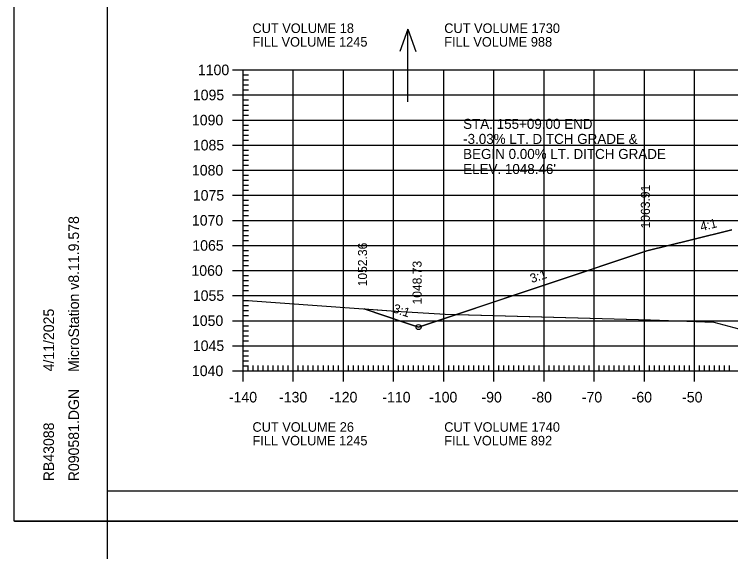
# Model space of a CAD drawing. Extents: x 1322838 to 1324533, y 339903 to 351025.
# Drawn here: x 1323450 to 1323592.8, y 344818.1 to 344925.2 of the extents above; entities that cross this region are included whole.
import ezdxf

# ---------------------------------------------------------------- set-up
doc = ezdxf.new("R2010")
doc.units = 0
for name, color, linetype in [('R_Axis', 7, 'Continuous'), ('R_Axis Annot', 7, 'Continuous'), ('R_Border', 7, 'Continuous'), ('R_Drive', 7, 'Continuous'), ('R_Exist Surface', 7, 'Continuous'), ('R_Fin Surface', 7, 'Continuous'), ('R_Grid', 7, 'Continuous'), ('R_No Plot', 7, 'Continuous'), ('R_Water Annot', 7, 'Continuous'), ('R_Xsect Elev', 7, 'Continuous'), ('R_Xsect Slope', 7, 'Continuous')]:
    doc.layers.add(name, color=color, linetype=linetype)

msp = doc.modelspace()

# ---------------------------------------------------------------- linework, layer by layer
at = {"layer": 'R_Axis'}
for p, q in [((1323493.48, 344914.14), (1323497.68, 344914.14)), ((1323495.58, 344854.14), (1323495.58, 344914.14)), ((1323495.58, 344913.14), (1323496.63, 344913.14)), ((1323495.58, 344912.14), (1323496.63, 344912.14)), ((1323495.58, 344911.14), (1323496.63, 344911.14)), ((1323495.58, 344910.14), (1323496.63, 344910.14)), ((1323493.48, 344909.14), (1323497.68, 344909.14)), ((1323495.58, 344908.14), (1323496.63, 344908.14)), ((1323495.58, 344907.14), (1323496.63, 344907.14)), ((1323495.58, 344906.14), (1323496.63, 344906.14)), ((1323495.58, 344905.14), (1323496.63, 344905.14)), ((1323493.48, 344904.14), (1323497.68, 344904.14)), ((1323495.58, 344903.14), (1323496.63, 344903.14)), ((1323495.58, 344902.14), (1323496.63, 344902.14)), ((1323495.58, 344901.14), (1323496.63, 344901.14)), ((1323495.58, 344900.14), (1323496.63, 344900.14)), ((1323493.48, 344899.14), (1323497.68, 344899.14)), ((1323495.58, 344898.14), (1323496.63, 344898.14)), ((1323495.58, 344897.14), (1323496.63, 344897.14)), ((1323495.58, 344896.14), (1323496.63, 344896.14)), ((1323495.58, 344895.14), (1323496.63, 344895.14)), ((1323493.48, 344894.14), (1323497.68, 344894.14)), ((1323495.58, 344893.14), (1323496.63, 344893.14)), ((1323495.58, 344892.14), (1323496.63, 344892.14)), ((1323495.58, 344891.14), (1323496.63, 344891.14)), ((1323495.58, 344890.14), (1323496.63, 344890.14)), ((1323493.48, 344889.14), (1323497.68, 344889.14)), ((1323495.58, 344888.14), (1323496.63, 344888.14)), ((1323495.58, 344887.14), (1323496.63, 344887.14)), ((1323495.58, 344886.14), (1323496.63, 344886.14)), ((1323495.58, 344885.14), (1323496.63, 344885.14)), ((1323493.48, 344884.14), (1323497.68, 344884.14)), ((1323495.58, 344883.14), (1323496.63, 344883.14)), ((1323495.58, 344882.14), (1323496.63, 344882.14)), ((1323495.58, 344881.14), (1323496.63, 344881.14)), ((1323495.58, 344880.14), (1323496.63, 344880.14)), ((1323493.48, 344879.14), (1323497.68, 344879.14)), ((1323495.58, 344878.14), (1323496.63, 344878.14)), ((1323495.58, 344877.14), (1323496.63, 344877.14)), ((1323495.58, 344876.14), (1323496.63, 344876.14)), ((1323495.58, 344875.14), (1323496.63, 344875.14)), ((1323493.48, 344874.14), (1323497.68, 344874.14)), ((1323495.58, 344873.14), (1323496.63, 344873.14)), ((1323495.58, 344872.14), (1323496.63, 344872.14)), ((1323495.58, 344871.14), (1323496.63, 344871.14)), ((1323495.58, 344870.14), (1323496.63, 344870.14)), ((1323493.48, 344869.14), (1323497.68, 344869.14)), ((1323495.58, 344868.14), (1323496.63, 344868.14)), ((1323495.58, 344867.14), (1323496.63, 344867.14)), ((1323495.58, 344866.14), (1323496.63, 344866.14)), ((1323495.58, 344865.14), (1323496.63, 344865.14)), ((1323493.48, 344864.14), (1323497.68, 344864.14)), ((1323495.58, 344863.14), (1323496.63, 344863.14)), ((1323495.58, 344862.14), (1323496.63, 344862.14)), ((1323495.58, 344861.14), (1323496.63, 344861.14)), ((1323495.58, 344860.14), (1323496.63, 344860.14)), ((1323493.48, 344859.14), (1323497.68, 344859.14)), ((1323495.58, 344858.14), (1323496.63, 344858.14)), ((1323495.58, 344857.14), (1323496.63, 344857.14)), ((1323495.58, 344852.04), (1323495.58, 344856.24)), ((1323495.58, 344856.14), (1323496.63, 344856.14)), ((1323495.58, 344855.14), (1323496.63, 344855.14)), ((1323496.58, 344854.14), (1323496.58, 344855.19)), ((1323497.58, 344854.14), (1323497.58, 344855.19)), ((1323498.58, 344854.14), (1323498.58, 344855.19)), ((1323499.58, 344854.14), (1323499.58, 344855.19)), ((1323500.58, 344854.14), (1323500.58, 344855.19)), ((1323501.58, 344854.14), (1323501.58, 344855.19)), ((1323502.58, 344854.14), (1323502.58, 344855.19)), ((1323503.58, 344854.14), (1323503.58, 344855.19)), ((1323504.58, 344854.14), (1323504.58, 344855.19)), ((1323505.58, 344852.04), (1323505.58, 344856.24)), ((1323506.58, 344854.14), (1323506.58, 344855.19)), ((1323507.58, 344854.14), (1323507.58, 344855.19)), ((1323508.58, 344854.14), (1323508.58, 344855.19)), ((1323509.58, 344854.14), (1323509.58, 344855.19)), ((1323510.58, 344854.14), (1323510.58, 344855.19)), ((1323511.58, 344854.14), (1323511.58, 344855.19)), ((1323512.58, 344854.14), (1323512.58, 344855.19)), ((1323513.58, 344854.14), (1323513.58, 344855.19)), ((1323514.58, 344854.14), (1323514.58, 344855.19)), ((1323515.58, 344852.04), (1323515.58, 344856.24)), ((1323516.58, 344854.14), (1323516.58, 344855.19)), ((1323517.58, 344854.14), (1323517.58, 344855.19)), ((1323518.58, 344854.14), (1323518.58, 344855.19)), ((1323519.58, 344854.14), (1323519.58, 344855.19)), ((1323520.58, 344854.14), (1323520.58, 344855.19)), ((1323521.58, 344854.14), (1323521.58, 344855.19)), ((1323522.58, 344854.14), (1323522.58, 344855.19)), ((1323523.58, 344854.14), (1323523.58, 344855.19)), ((1323524.58, 344854.14), (1323524.58, 344855.19)), ((1323525.58, 344852.04), (1323525.58, 344856.24)), ((1323526.58, 344854.14), (1323526.58, 344855.19)), ((1323527.58, 344854.14), (1323527.58, 344855.19)), ((1323528.58, 344854.14), (1323528.58, 344855.19)), ((1323529.58, 344854.14), (1323529.58, 344855.19)), ((1323530.58, 344854.14), (1323530.58, 344855.19)), ((1323531.58, 344854.14), (1323531.58, 344855.19)), ((1323532.58, 344854.14), (1323532.58, 344855.19)), ((1323533.58, 344854.14), (1323533.58, 344855.19)), ((1323534.58, 344854.14), (1323534.58, 344855.19)), ((1323535.58, 344852.04), (1323535.58, 344856.24)), ((1323536.58, 344854.14), (1323536.58, 344855.19)), ((1323537.58, 344854.14), (1323537.58, 344855.19)), ((1323538.58, 344854.14), (1323538.58, 344855.19)), ((1323539.58, 344854.14), (1323539.58, 344855.19)), ((1323540.58, 344854.14), (1323540.58, 344855.19)), ((1323541.58, 344854.14), (1323541.58, 344855.19)), ((1323542.58, 344854.14), (1323542.58, 344855.19)), ((1323543.58, 344854.14), (1323543.58, 344855.19)), ((1323544.58, 344854.14), (1323544.58, 344855.19)), ((1323545.58, 344852.04), (1323545.58, 344856.24)), ((1323546.58, 344854.14), (1323546.58, 344855.19)), ((1323547.58, 344854.14), (1323547.58, 344855.19)), ((1323548.58, 344854.14), (1323548.58, 344855.19)), ((1323549.58, 344854.14), (1323549.58, 344855.19)), ((1323550.58, 344854.14), (1323550.58, 344855.19)), ((1323551.58, 344854.14), (1323551.58, 344855.19)), ((1323552.58, 344854.14), (1323552.58, 344855.19)), ((1323553.58, 344854.14), (1323553.58, 344855.19)), ((1323554.58, 344854.14), (1323554.58, 344855.19)), ((1323555.58, 344852.04), (1323555.58, 344856.24)), ((1323556.58, 344854.14), (1323556.58, 344855.19)), ((1323557.58, 344854.14), (1323557.58, 344855.19)), ((1323558.58, 344854.14), (1323558.58, 344855.19)), ((1323559.58, 344854.14), (1323559.58, 344855.19)), ((1323560.58, 344854.14), (1323560.58, 344855.19)), ((1323561.58, 344854.14), (1323561.58, 344855.19)), ((1323562.58, 344854.14), (1323562.58, 344855.19)), ((1323563.58, 344854.14), (1323563.58, 344855.19)), ((1323564.58, 344854.14), (1323564.58, 344855.19)), ((1323565.58, 344852.04), (1323565.58, 344856.24)), ((1323566.58, 344854.14), (1323566.58, 344855.19)), ((1323567.58, 344854.14), (1323567.58, 344855.19)), ((1323568.58, 344854.14), (1323568.58, 344855.19)), ((1323569.58, 344854.14), (1323569.58, 344855.19)), ((1323570.58, 344854.14), (1323570.58, 344855.19)), ((1323571.58, 344854.14), (1323571.58, 344855.19)), ((1323572.58, 344854.14), (1323572.58, 344855.19)), ((1323573.58, 344854.14), (1323573.58, 344855.19)), ((1323574.58, 344854.14), (1323574.58, 344855.19)), ((1323575.58, 344852.04), (1323575.58, 344856.24)), ((1323576.58, 344854.14), (1323576.58, 344855.19)), ((1323577.58, 344854.14), (1323577.58, 344855.19)), ((1323578.58, 344854.14), (1323578.58, 344855.19)), ((1323579.58, 344854.14), (1323579.58, 344855.19)), ((1323580.58, 344854.14), (1323580.58, 344855.19)), ((1323581.58, 344854.14), (1323581.58, 344855.19)), ((1323582.58, 344854.14), (1323582.58, 344855.19)), ((1323583.58, 344854.14), (1323583.58, 344855.19)), ((1323584.58, 344854.14), (1323584.58, 344855.19)), ((1323585.58, 344852.04), (1323585.58, 344856.24)), ((1323586.58, 344854.14), (1323586.58, 344855.19)), ((1323587.58, 344854.14), (1323587.58, 344855.19)), ((1323588.58, 344854.14), (1323588.58, 344855.19)), ((1323589.58, 344854.14), (1323589.58, 344855.19)), ((1323590.58, 344854.14), (1323590.58, 344855.19)), ((1323591.58, 344854.14), (1323591.58, 344855.19)), ((1323592.58, 344854.14), (1323592.58, 344855.19)), ((1323493.48, 344854.14), (1323497.68, 344854.14)), ((1323495.58, 344854.14), (1323915.58, 344854.14))]:
    msp.add_line(p, q, dxfattribs=at)
at = {"layer": 'R_Border'}
for p, q in [((1323468.58, 344830.14), (1323468.58, 345138.33)), ((1323468.58, 344830.14), (1323468.58, 344830.14)), ((1323942.85, 344830.14), (1323468.58, 344830.14))]:
    msp.add_line(p, q, dxfattribs=at)
at = {"layer": 'R_Exist Surface'}
msp.add_lwpolyline([(1323495.58, 344868.23), (1323526.05, 344866.04), (1323535.88, 344865.46), (1323576.79, 344864.33), (1323589.42, 344863.87), (1323598.4, 344861.44)], dxfattribs=at)
at = {"layer": 'R_Fin Surface'}
msp.add_lwpolyline([(1323519.69, 344866.49), (1323527.99, 344863.73), (1323530.57, 344862.87), (1323576.08, 344878.04), (1323584.97, 344880.26), (1323592.99, 344882.27)], dxfattribs=at)
at = {"layer": 'R_Grid'}
for p, q in [((1323495.58, 344914.14), (1323915.58, 344914.14)), ((1323495.58, 344854.14), (1323495.58, 344914.14)), ((1323505.58, 344854.14), (1323505.58, 344914.14)), ((1323515.58, 344854.14), (1323515.58, 344914.14)), ((1323525.58, 344854.14), (1323525.58, 344914.14)), ((1323535.58, 344854.14), (1323535.58, 344914.14)), ((1323545.58, 344854.14), (1323545.58, 344914.14)), ((1323555.58, 344854.14), (1323555.58, 344914.14)), ((1323565.58, 344854.14), (1323565.58, 344914.14)), ((1323575.58, 344854.14), (1323575.58, 344914.14)), ((1323585.58, 344854.14), (1323585.58, 344914.14)), ((1323495.58, 344909.14), (1323915.58, 344909.14)), ((1323495.58, 344904.14), (1323915.58, 344904.14)), ((1323495.58, 344899.14), (1323915.58, 344899.14)), ((1323495.58, 344894.14), (1323915.58, 344894.14)), ((1323495.58, 344889.14), (1323915.58, 344889.14)), ((1323495.58, 344884.14), (1323915.58, 344884.14)), ((1323495.58, 344879.14), (1323915.58, 344879.14)), ((1323495.58, 344874.14), (1323915.58, 344874.14)), ((1323495.58, 344869.14), (1323915.58, 344869.14)), ((1323495.58, 344864.14), (1323915.58, 344864.14)), ((1323495.58, 344859.14), (1323915.58, 344859.14)), ((1323495.58, 344854.14), (1323915.58, 344854.14))]:
    msp.add_line(p, q, dxfattribs=at)
at = {"layer": 'R_No Plot'}
for p, q in [((1323468.58, 344745.73), (1323468.58, 344830.14)), ((1323449.98, 344824.17), (1323949.98, 344824.17))]:
    msp.add_line(p, q, dxfattribs=at)
for points in [[(1323449.97, 345144.17), (1323949.98, 345144.17), (1323949.98, 344824.16), (1323449.97, 344824.16)], [(1323819.46, 345138.33), (1323848.89, 345138.33), (1323848.89, 345123.51), (1323873.06, 345123.51), (1323907.86, 345123.51), (1323907.86, 345074.5), (1323942.67, 345074.5), (1323942.85, 344830.14), (1323468.58, 344830.14), (1323468.58, 345138.33)], [(1323519.69, 344866.49), (1323526.05, 344866.04), (1323535.88, 344865.46), (1323538.15, 344865.4), (1323530.57, 344862.87), (1323527.99, 344863.73)]]:
    msp.add_lwpolyline(points, close=True, dxfattribs=at)
msp.add_lwpolyline([(1323592.99, 344882.27), (1323584.97, 344880.26), (1323576.08, 344878.04), (1323538.15, 344865.4), (1323576.79, 344864.33), (1323589.42, 344863.87), (1323598.4, 344861.44)], dxfattribs=at)
msp.add_circle((1323530.57, 344862.87), 0.5, dxfattribs=at)
at = {"layer": 'R_Water Annot'}
for p, q in [((1323528.42, 344922.26), (1323526.8, 344917.82)), ((1323528.42, 344907.77), (1323528.42, 344922.26)), ((1323528.42, 344922.26), (1323530.03, 344917.82))]:
    msp.add_line(p, q, dxfattribs=at)

# ---------------------------------------------------------------- texts
at = {"layer": 'R_Axis Annot'}
for s, height, p in [('CUT VOLUME 18', 1.9043, (1323497.45, 344921.5)), ('CUT VOLUME 1730', 1.9043, (1323535.68, 344921.5)), ('FILL VOLUME 1245', 1.9043, (1323497.45, 344918.78)), ('FILL VOLUME 988', 1.9043, (1323535.68, 344918.78)), ('1100', 2.1, (1323486.57, 344913.09)), ('1095', 2.1, (1323485.56, 344908.09)), ('1090', 2.1, (1323485.38, 344903.09)), ('1085', 2.1, (1323485.56, 344898.09)), ('1080', 2.1, (1323485.38, 344893.09)), ('1075', 2.1, (1323485.56, 344888.09)), ('1070', 2.1, (1323485.38, 344883.09)), ('1065', 2.1, (1323485.46, 344878.09)), ('1060', 2.1, (1323485.28, 344873.09)), ('1055', 2.1, (1323485.56, 344868.09)), ('1050', 2.1, (1323485.38, 344863.09)), ('1045', 2.1, (1323485.56, 344858.09)), ('1040', 2.1, (1323485.38, 344853.09)), ('-140', 2.1, (1323492.75, 344847.84)), ('-130', 2.1, (1323502.75, 344847.84)), ('-120', 2.1, (1323512.75, 344847.84)), ('-110', 2.1, (1323523.34, 344847.84)), ('-100', 2.1, (1323532.67, 344847.84)), ('-90', 2.1, (1323543.1, 344847.84)), ('-80', 2.1, (1323553.1, 344847.84)), ('-70', 2.1, (1323563.1, 344847.84)), ('-60', 2.1, (1323573.05, 344847.84)), ('-50', 2.1, (1323583.1, 344847.84)), ('CUT VOLUME 26', 1.9043, (1323497.45, 344841.99)), ('CUT VOLUME 1740', 1.9043, (1323535.68, 344841.99)), ('FILL VOLUME 1245', 1.9043, (1323497.45, 344839.27)), ('FILL VOLUME 892', 1.9043, (1323535.68, 344839.27))]:
    msp.add_text(s, height=height, dxfattribs=at).set_placement(p)
at = {"layer": 'R_Border'}
for s, p in [('MicroStation v8.11.9.578', (1323462.87, 344853.92)), ('4/11/2025', (1323457.88, 344854.03)), ('R090581.DGN', (1323462.87, 344832.12)), ('RB43088', (1323457.88, 344832.12))]:
    msp.add_text(s, height=2.1, rotation=90, dxfattribs=at).set_placement(p)
at = {"layer": 'R_Drive'}
for s, p in [('STA. 155+09.00 END ', (1323539.45, 344902.38)), ('-3.03% LT. DITCH GRADE &', (1323539.45, 344899.38)), ('BEGIN 0.00% LT. DITCH GRADE', (1323539.45, 344896.38)), ("ELEV. 1048.46'", (1323539.45, 344893.38))]:
    msp.add_text(s, height=1.9999, dxfattribs=at).set_placement(p)
at = {"layer": 'R_Xsect Elev'}
for s, p in [('1063.91', (1323576.68, 344882.54)), ('1052.36', (1323520.29, 344870.99)), ('1048.73', (1323531.17, 344867.37))]:
    msp.add_text(s, height=1.8, rotation=90, dxfattribs=at).set_placement(p)
at = {"layer": 'R_Xsect Slope'}
for s, rotation, p in [('4:1', 14.0358, (1323586.94, 344881.97)), ('3:1', 18.4353, (1323553.13, 344871.63)), ('3:1', 341.5667, (1323525.32, 344865.85))]:
    msp.add_text(s, height=1.8, rotation=rotation, dxfattribs=at).set_placement(p)

doc.saveas('drawing.dxf')
